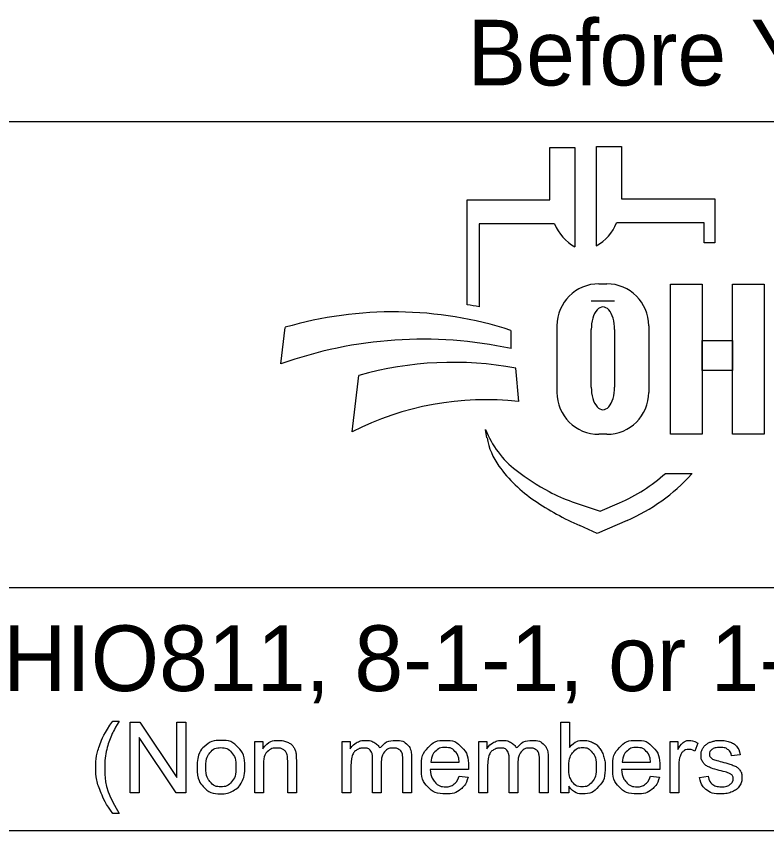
# Model space of a CAD drawing. Extents: x 0 to 34, y 0 to 22.
# Drawn here: x 2.596 to 4.196, y 2.143 to 3.88 of the extents above; entities that cross this region are included whole.
import ezdxf

# ---------------------------------------------------------------- set-up
doc = ezdxf.new("R2010")
doc.units = 0
doc.layers.add('SH_Data', color=7, linetype='Continuous')
doc.layers.add('SH_Text', color=7, linetype='Continuous')

msp = doc.modelspace()

# ---------------------------------------------------------------- linework, layer by layer
at = {"layer": 'SH_Data'}
for p, q in [((2.3775, 3.6553), (6.6275, 3.6553)), ((6.6275, 2.6607), (2.3775, 2.6607)), ((6.6275, 2.1428), (2.3775, 2.1428))]:
    msp.add_line(p, q, dxfattribs=at)
at = {"layer": 'SH_Text'}
for p, q in [((3.7335, 3.4883), (3.7335, 3.5998)), ((3.7335, 3.5998), (3.7872, 3.5998)), ((3.7872, 3.5998), (3.7872, 3.3877)), ((3.8329, 3.39), (3.8329, 3.6021)), ((3.8329, 3.6021), (3.8865, 3.6021)), ((3.8865, 3.6021), (3.8865, 3.4906)), ((3.5576, 3.2644), (3.5576, 3.4883)), ((3.5576, 3.4883), (3.7335, 3.4883)), ((3.8865, 3.4906), (4.0857, 3.4906)), ((4.0857, 3.4906), (4.0857, 3.3968)), ((4.0625, 3.4392), (3.8761, 3.4392)), ((4.0625, 3.3968), (4.0625, 3.4392)), ((3.5828, 3.4369), (3.5828, 3.26)), ((3.7439, 3.4369), (3.5828, 3.4369)), ((4.0857, 3.3968), (4.0625, 3.3968)), ((3.8385, 3.3091), (3.8551, 3.3091)), ((3.8718, 3.2721), (3.822, 3.2721)), ((3.1602, 3.1381), (3.1696, 3.2162)), ((3.7491, 3.0776), (3.7491, 3.2196)), ((3.9445, 3.2196), (3.9445, 3.0776)), ((3.6509, 3.2097), (3.6509, 3.1709)), ((3.822, 3.089), (3.822, 3.2114)), ((3.8718, 3.2114), (3.8718, 3.089)), ((3.6608, 3.1291), (3.6671, 3.0582)), ((3.312, 2.9936), (3.3267, 3.1137)), ((3.5997, 2.9807), (3.5967, 2.9986)), ((3.8551, 2.9882), (3.8385, 2.9882)), ((3.98, 2.9048), (4.0375, 2.9048)), ((3.7816, 2.8444), (3.841, 2.8239)), ((3.841, 2.8239), (3.8821, 2.8417)), ((3.8983, 2.8044), (3.835, 2.7769)), ((3.835, 2.7769), (3.7976, 2.7934))]:
    msp.add_line(p, q, dxfattribs=at)
for points in [[(3.991, 3.3081), (4.0589, 3.3081), (4.0589, 2.9881), (3.991, 2.9881)], [(4.1231, 3.3081), (4.1911, 3.3081), (4.1911, 2.9881), (4.1231, 2.9881)], [(4.0589, 3.1882), (4.1231, 3.1882), (4.1231, 3.1242), (4.0589, 3.1242)]]:
    msp.add_lwpolyline(points, close=True, dxfattribs=at)
for points in [[(2.8021, 2.3766), (2.8153, 2.3766)], [(2.8389, 2.2239), (2.8389, 2.3741), (2.8592, 2.3741), (2.9382, 2.2561), (2.9382, 2.3741), (2.9572, 2.3741), (2.9572, 2.2239), (2.9369, 2.2239), (2.8579, 2.3419), (2.8579, 2.2239), (2.8389, 2.2239)], [(3.7743, 2.2239), (3.7573, 2.2239), (3.7573, 2.3741), (3.7757, 2.3741), (3.7757, 2.3206)], [(3.1048, 2.2239), (3.1048, 2.3328), (3.1214, 2.3328), (3.1214, 2.3173)], [(3.2912, 2.2239), (3.2912, 2.3328), (3.3077, 2.3328), (3.3077, 2.3174)], [(3.5826, 2.2239), (3.5826, 2.3328), (3.5991, 2.3328), (3.5991, 2.3174)], [(3.9904, 2.2239), (3.9904, 2.3328), (4.007, 2.3328), (4.007, 2.3163)], [(4.0495, 2.3293), (4.043, 2.3122)], [(3.3743, 2.2871), (3.3743, 2.2239), (3.3559, 2.2239), (3.3559, 2.2946)], [(3.4388, 2.2986), (3.4388, 2.2239), (3.4203, 2.2239), (3.4203, 2.2924)], [(3.6657, 2.2871), (3.6657, 2.2239), (3.6473, 2.2239), (3.6473, 2.2946)], [(3.7301, 2.2986), (3.7301, 2.2239), (3.7117, 2.2239), (3.7117, 2.2924)], [(4.1394, 2.3046), (4.1213, 2.3022)], [(3.1233, 2.2833), (3.1233, 2.2239), (3.1048, 2.2239)], [(3.1932, 2.2908), (3.1932, 2.2239), (3.1748, 2.2239), (3.1748, 2.2901)], [(3.3097, 2.2803), (3.3097, 2.2239), (3.2912, 2.2239)], [(3.4799, 2.2887), (3.5406, 2.2887)], [(3.601, 2.2803), (3.601, 2.2239), (3.5826, 2.2239)], [(3.8879, 2.2887), (3.9486, 2.2887)], [(4.0088, 2.2809), (4.0088, 2.2239), (3.9904, 2.2239)], [(3.56, 2.2736), (3.4788, 2.2736)], [(3.5404, 2.2591), (3.5595, 2.2567)], [(3.968, 2.2736), (3.8868, 2.2736)], [(3.9484, 2.2591), (3.9675, 2.2567)], [(4.053, 2.2564), (4.0712, 2.2593)], [(3.7743, 2.2375), (3.7743, 2.2239)], [(2.8153, 2.1798), (2.8021, 2.1798)]]:
    msp.add_lwpolyline(points, dxfattribs=at)
for centre, radius, start, end in [((3.7847, 3.476), 0.0985, 299.2531, 338.0704), ((3.8353, 3.4736), 0.0985, 201.9296, 240.7469), ((3.8385, 3.2196), 0.0895, 90, 180), ((3.8551, 3.2196), 0.0895, 0, 90), ((3.3997, 2.4302), 0.8191, 72.1402, 106.3144), ((3.4295, 2.4554), 0.8191, 79.2074, 81.0007), ((3.4628, 2.2991), 0.8919, 77.8238, 109.8274), ((3.5267, 2.4094), 0.7322, 79.44, 105.8467), ((3.8385, 3.0776), 0.0895, 180, 270), ((3.8551, 3.0776), 0.0895, 270, 0), ((3.5987, 2.4262), 0.6357, 83.8248, 116.8021), ((3.7841, 3.0707), 0.2008, 201.0457, 232.5314), ((3.741, 3.0048), 0.1433, 189.6817, 216.0884), ((3.8747, 3.1022), 0.3088, 216.0884, 235.7167), ((3.9766, 3.3219), 0.5173, 232.5314, 241.794), ((3.7387, 3.1722), 0.3602, 293.4582, 312.0712), ((3.7387, 3.1722), 0.401, 293.4582, 317.8286), ((3.8914, 3.1631), 0.3371, 241.794, 250.9821), ((4.0412, 3.3465), 0.6044, 235.7167, 246.2325)]:
    msp.add_arc(centre, radius, start, end, dxfattribs=at)
for centre, start_param, end_param in [((3.8469, 3.2114), 4.712389, 7.853982), ((3.8469, 3.089), 1.570796, 4.712389)]:
    msp.add_ellipse(centre, major_axis=(0, 0.0484), ratio=0.514403, start_param=start_param, end_param=end_param, dxfattribs=at)
for points in [[(2.8021, 2.1798), (2.7869, 2.199), (2.7763, 2.2248), (2.7657, 2.2506), (2.7657, 2.2783), (2.7657, 2.3026), (2.7736, 2.325), (2.7829, 2.3509), (2.8021, 2.3766)], [(2.8153, 2.3766), (2.8029, 2.3553), (2.7989, 2.3462), (2.7927, 2.332), (2.7891, 2.3167), (2.7847, 2.2975), (2.7847, 2.2782), (2.7847, 2.2289), (2.8153, 2.1798)], [(2.9814, 2.2783), (2.9814, 2.3085), (2.9981, 2.3231), (3.0122, 2.3352), (3.0323, 2.3352), (3.0547, 2.3352), (3.069, 2.3205), (3.0832, 2.3058), (3.0832, 2.2799), (3.0832, 2.2589), (3.0769, 2.2469), (3.0706, 2.2348), (3.0586, 2.2282), (3.0466, 2.2215), (3.0323, 2.2215), (3.0095, 2.2215), (2.9954, 2.2362), (2.9814, 2.2508), (2.9814, 2.2783)], [(3.1214, 2.3173), (3.1334, 2.3352), (3.156, 2.3352), (3.1659, 2.3352), (3.1741, 2.3316), (3.1823, 2.3281), (3.1864, 2.3224), (3.1905, 2.3166), (3.1922, 2.3087), (3.1932, 2.3036), (3.1932, 2.2908)], [(3.3077, 2.3174), (3.3128, 2.3254), (3.3214, 2.3303), (3.3299, 2.3352), (3.3407, 2.3352), (3.3528, 2.3352), (3.3606, 2.3301), (3.3683, 2.3251), (3.3715, 2.3161), (3.3844, 2.3352), (3.4051, 2.3352), (3.4213, 2.3352), (3.43, 2.3262), (3.4388, 2.3172), (3.4388, 2.2986)], [(3.5595, 2.2567), (3.555, 2.24), (3.5428, 2.2307), (3.5306, 2.2215), (3.5117, 2.2215), (3.4878, 2.2215), (3.4738, 2.2362), (3.4598, 2.2509), (3.4598, 2.2774), (3.4598, 2.3049), (3.474, 2.32), (3.4881, 2.3352), (3.5106, 2.3352), (3.5324, 2.3352), (3.5463, 2.3203), (3.5601, 2.3055), (3.5601, 2.2785), (3.5601, 2.2769), (3.56, 2.2736)], [(3.5991, 2.3174), (3.6042, 2.3254), (3.6127, 2.3303), (3.6212, 2.3352), (3.6321, 2.3352), (3.6442, 2.3352), (3.6519, 2.3301), (3.6597, 2.3251), (3.6628, 2.3161), (3.6758, 2.3352), (3.6965, 2.3352), (3.7127, 2.3352), (3.7214, 2.3262), (3.7301, 2.3172), (3.7301, 2.2986)], [(3.7757, 2.3206), (3.7874, 2.3352), (3.8055, 2.3352), (3.8155, 2.3352), (3.8245, 2.3311), (3.8335, 2.3271), (3.8392, 2.3198), (3.845, 2.3124), (3.8483, 2.3021), (3.8516, 2.2918), (3.8516, 2.28), (3.8516, 2.252), (3.8378, 2.2368), (3.8239, 2.2215), (3.8046, 2.2215), (3.7853, 2.2215), (3.7743, 2.2375)], [(3.9675, 2.2567), (3.963, 2.24), (3.9508, 2.2307), (3.9386, 2.2215), (3.9196, 2.2215), (3.8958, 2.2215), (3.8818, 2.2362), (3.8678, 2.2509), (3.8678, 2.2774), (3.8678, 2.3049), (3.882, 2.32), (3.8961, 2.3352), (3.9186, 2.3352), (3.9404, 2.3352), (3.9543, 2.3203), (3.9681, 2.3055), (3.9681, 2.2785), (3.9681, 2.2769), (3.968, 2.2736)], [(4.007, 2.3163), (4.0133, 2.3278), (4.0187, 2.3315), (4.0241, 2.3352), (4.0305, 2.3352), (4.0398, 2.3352), (4.0495, 2.3293)], [(4.0712, 2.2593), (4.0727, 2.2483), (4.0798, 2.2425), (4.0868, 2.2366), (4.0995, 2.2366), (4.1122, 2.2366), (4.1184, 2.2418), (4.1245, 2.247), (4.1245, 2.254), (4.1245, 2.2602), (4.1191, 2.2638), (4.1153, 2.2663), (4.1002, 2.2701), (4.0799, 2.2752), (4.072, 2.2789), (4.0642, 2.2827), (4.0601, 2.2893), (4.0561, 2.2959), (4.0561, 2.3038), (4.0561, 2.3111), (4.0594, 2.3173), (4.0628, 2.3235), (4.0685, 2.3276), (4.0728, 2.3308), (4.0803, 2.333), (4.0877, 2.3352), (4.0962, 2.3352), (4.109, 2.3352), (4.1187, 2.3315), (4.1284, 2.3278), (4.133, 2.3215), (4.1377, 2.3152), (4.1394, 2.3046)], [(3.0003, 2.2783), (3.0003, 2.2574), (3.0094, 2.247), (3.0185, 2.2366), (3.0323, 2.2366), (3.046, 2.2366), (3.0551, 2.2471), (3.0642, 2.2575), (3.0642, 2.279), (3.0642, 2.2991), (3.0551, 2.3095), (3.0459, 2.3199), (3.0323, 2.3199), (3.0185, 2.3199), (3.0094, 2.3096), (3.0003, 2.2992), (3.0003, 2.2783)], [(3.1748, 2.2901), (3.1748, 2.3013), (3.1726, 2.3069), (3.1705, 2.3125), (3.165, 2.3158), (3.1595, 2.3191), (3.1521, 2.3191), (3.1404, 2.3191), (3.1318, 2.3117), (3.1233, 2.3042), (3.1233, 2.2833)], [(3.3559, 2.2946), (3.3559, 2.3069), (3.3514, 2.313), (3.3469, 2.3191), (3.3366, 2.3191), (3.3288, 2.3191), (3.3222, 2.315), (3.3156, 2.311), (3.3126, 2.3031), (3.3097, 2.2952), (3.3097, 2.2803)], [(3.4203, 2.2924), (3.4203, 2.3035), (3.4185, 2.3083), (3.4168, 2.3132), (3.412, 2.3162), (3.4073, 2.3191), (3.401, 2.3191), (3.3895, 2.3191), (3.3819, 2.3115), (3.3743, 2.3039), (3.3743, 2.2871)], [(3.5406, 2.2887), (3.5394, 2.3025), (3.5337, 2.3094), (3.5249, 2.3201), (3.5108, 2.3201), (3.4981, 2.3201), (3.4894, 2.3115), (3.4808, 2.303), (3.4799, 2.2887)], [(3.6473, 2.2946), (3.6473, 2.3069), (3.6428, 2.313), (3.6383, 2.3191), (3.628, 2.3191), (3.6202, 2.3191), (3.6136, 2.315), (3.607, 2.311), (3.604, 2.3031), (3.601, 2.2952), (3.601, 2.2803)], [(3.7117, 2.2924), (3.7117, 2.3035), (3.7099, 2.3083), (3.7081, 2.3132), (3.7034, 2.3162), (3.6987, 2.3191), (3.6923, 2.3191), (3.6809, 2.3191), (3.6733, 2.3115), (3.6657, 2.3039), (3.6657, 2.2871)], [(3.7741, 2.2792), (3.7741, 2.2596), (3.7794, 2.2509), (3.7881, 2.2366), (3.8029, 2.2366), (3.815, 2.2366), (3.8238, 2.2471), (3.8326, 2.2576), (3.8326, 2.2784), (3.8326, 2.2998), (3.8241, 2.3099), (3.8157, 2.3201), (3.8038, 2.3201), (3.7917, 2.3201), (3.7829, 2.3096), (3.7741, 2.299), (3.7741, 2.2792)], [(3.9486, 2.2887), (3.9474, 2.3025), (3.9417, 2.3094), (3.9328, 2.3201), (3.9188, 2.3201), (3.9061, 2.3201), (3.8974, 2.3115), (3.8888, 2.303), (3.8879, 2.2887)], [(4.043, 2.3122), (4.0363, 2.3162), (4.0295, 2.3162), (4.0235, 2.3162), (4.0187, 2.3125), (4.0139, 2.3089), (4.0119, 2.3024), (4.0088, 2.2926), (4.0088, 2.2809)], [(4.1213, 2.3022), (4.1201, 2.3106), (4.1142, 2.3153), (4.1083, 2.3201), (4.0975, 2.3201), (4.0848, 2.3201), (4.0794, 2.3159), (4.0739, 2.3116), (4.0739, 2.306), (4.0739, 2.3024), (4.0762, 2.2995), (4.0785, 2.2966), (4.0833, 2.2946), (4.086, 2.2936), (4.0996, 2.2899), (4.1192, 2.2847), (4.1269, 2.2813), (4.1347, 2.278), (4.1391, 2.2717), (4.1435, 2.2653), (4.1435, 2.2559), (4.1435, 2.2467), (4.1381, 2.2386), (4.1327, 2.2304), (4.1226, 2.226), (4.1124, 2.2215), (4.0996, 2.2215), (4.0784, 2.2215), (4.0672, 2.2303), (4.0561, 2.2391), (4.053, 2.2564)], [(3.4788, 2.2736), (3.4799, 2.2557), (3.489, 2.2462), (3.4981, 2.2366), (3.5117, 2.2366), (3.5219, 2.2366), (3.5291, 2.242), (3.5362, 2.2473), (3.5404, 2.2591)], [(3.8868, 2.2736), (3.8879, 2.2557), (3.897, 2.2462), (3.9061, 2.2366), (3.9197, 2.2366), (3.9299, 2.2366), (3.937, 2.242), (3.9442, 2.2473), (3.9484, 2.2591)]]:
    msp.add_open_spline(points, degree=3, dxfattribs=at)

# ---------------------------------------------------------------- texts
for s, p in [('Before You Dig', (3.5583, 3.7321)), ('OHIO811, 8-1-1, or 1-800-362-2764', (2.422, 2.4406))]:
    msp.add_text(s, height=0.14, dxfattribs=at).set_placement(p)

doc.saveas('drawing.dxf')
